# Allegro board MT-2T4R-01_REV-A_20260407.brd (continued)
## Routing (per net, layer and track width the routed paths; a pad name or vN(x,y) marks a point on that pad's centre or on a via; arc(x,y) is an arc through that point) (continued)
VDD12_MEM: length 12.6
  BOTTOM w0.2: 19.06,29.05 19.06,29.05 R64.2 C151.2
  BOTTOM w0.25: v2(20.7,9.01) U21.A9 21.13,9.44 v2(21.13,9.44) 21.13,9.87 U21.A11 v2(20.7,9.87) ; v2(20.7,9.01) U21.C9 U21.C11 v2(20.7,9.87) ; v2(20.7,9.01) 20.7,9.01 U21.B10 20.7,9.87 v2(20.7,9.87) ; U21.E13 v2(19.41,10.3) ; U21.D16 U21.E15
  BOTTOM w0.254: R87.2 C225.1 22.3,7.6 22.4,7.5 C223.1 22.05,7.05 21.7,7.4 21.7,8.44 U21.A9 ; U21.B10 v2(21.13,9.44) ; U21.E15 v2(19.41,11.18) ; U21.E11 v2(19.41,10.3)
  vias: v1(21.93,23.78) v1(21.99,24.12) v1(21.96,23.47) v1(22.24,23.79) v1(22.31,24.18) v1(22.28,23.4) v1(22.51,23.94) v1(22.5,23.61) v1(22.73,23.4) v1(22.79,23.7)
VIN_12V: length 12.8
  TOP w0.2: R102.1 v2(3.99,9.1)
  TOP w0.25: 6.38,18.52 6.57,18.33
  03-POWER w0.15: v2(6.66,18.17) 6.22,18.17 5.86,17.8 5.86,16.39 3.99,14.52 v2(3.99,9.1)
BOOT_SEL0: length 0.6
  TOP w0.3: 15.14,7.54 15.14,7.69 v2(15.11,7.72)
  BOTTOM w0.254: U21.P6 v2(15.11,7.72)
BOOT_SEL1: length 8.9
  TOP w0.3: 15.14,6.64 15.14,6.83 v2(15.11,6.86)
  BOTTOM w0.1: U21.N5 15.54,7.29 v2(15.11,6.86) 14.78,6.53 14.59,6.53 14.41,6.71 14.12,6.71 13.56,6.15 13.21,6.15 13.06,6.3 12.82,6.3 12.25,5.73 TP36.1 11.6,3.85 10.35,3.85 10.25,3.75 J3.3
BOOT_SEL2: length 1.3
  TOP w0.4: R100.2 15.14,5.97 v2(15.11,6)
  BOTTOM w0.1: v2(15.11,6) 15.54,6.42 U21.P4
BUCK_1V8: length 46.7
  TOP w0.25: v2(14.25,13.74) 14.15,13.64 C247.1
  TOP w0.3: v2(17.26,8.15) 17.45,7.96 C229.1 ; FB17.2 18.12,4.91 v2(18.12,5.1) 18.25,5.22 R94.2 R93.2 ; v2(15.97,12.88) 15.25,12.88 C232.1 ; v2(12.95,8.15) 13.37,7.73 C234.1
  TOP w0.35: FB16.1 C194.1 22.1,10.2 v2(21.88,9.98)
  03-POWER w0.1: v1(4.17,39.56) 4.17,39.56 9.64,39.56 v1(10.94,38.27) 12.22,39.55 12.22,39.56 20.66,39.56 v1(20.67,39.57)
  BOTTOM w0.1: U16.1 v1(20.67,39.57) ; U8.1 v1(4.17,39.56) ; v1(10.94,38.27) 10.94,36.01 10.58,35.66 C146.2
  BOTTOM w0.15: v2(11.67,6.04) 11.29,5.66 11.29,4.59 TP43.1 10.8,4.1 10.25,4.1 9.75,3.6 J3.4
  BOTTOM w0.2: C146.2 10.53,36.2 10.53,38.42 10.86,38.76 11.46,38.76 11.72,39.02 11.72,39.37 C140.2 R75.2
  BOTTOM w0.25: v2(14.25,13.74) U21.T20 U21.P20 ; v2(17.26,8.15) 17.26,8.15 U21.L7 ; U21.R17 U21.N17 v2(15.97,12.88)
  BOTTOM w0.254: U21.K8 v2(17.26,8.15) ; U21.AC3 v2(11.67,6.04) ; U21.T8 v2(14.68,8.15) ; U21.H2 v2(18.12,5.1) ; U21.AA7 v2(12.95,8.15) ; U21.C13 20.45,10.73 20.7,10.48 U21.B12 21.54,10.3 21.85,9.98 v2(21.88,9.98)
  BOTTOM w0.3: C146.2 9.98,35.28 v1(9.98,35.28) 9.98,35.15 v1(10.14,35)
  vias: v1(9.43,34.99) v1(9.47,34.38) v1(9.62,34.68) v1(9.66,35.27) v1(9.79,34.97) v1(9.8,34.39) v1(9.95,34.7) v1(10.13,34.45) v1(10.29,35.28) v1(10.28,34.72) v3(12.1,9.44)
BUCK_3V3: length 117.6
  TOP w0.3: R103.1 13.03,12.41 13.38,12.06 15.33,12.06 15.54,12.28 C193.1 15.97,12.08 v2(15.97,12.02) ; v2(13.39,8.58) 13.39,8.59 R101.2 13.33,8.99 13.78,8.99 14,8.77 C237.1 14.08,8.75 v2(14.25,8.58)
  TOP w0.35: R101.2 12.42,8.82 11.65,8.05 U19.8 11.35,8.22 11.35,9.71 12.26,10.62 12.26,12.25 R103.1
  TOP w0.4: v2(8.17,17.54) v2(8.61,17.54) ; v2(21.69,16.78) 21.26,16.78 v2(21.25,16.79)
  TOP w0.5: FB13.1 7.11,6.58 ; 7.11,6.58 7.21,6.68 9.54,6.68 C57.1 9.72,6.84 10.61,6.84 C254.1 11.18,7.41 U19.8 ; 7.11,6.58 6.49,7.2 6.49,8.86 7.64,10 v2(7.64,12.31) v2(7.64,12.79)
  03-POWER w0.4: v2(21.69,16.78) 21.26,16.78 v2(21.25,16.79) 21.25,25.39 21.05,25.59 21.05,28.87 21.68,29.5 v1(21.68,31.06) 22.82,32.19 22.82,40.19 21.63,41.38 4.23,41.38 2.84,39.98 2.84,36.14 3.69,35.29 4.39,35.29 v1(4.39,35.27) 4.71,34.95 v1(4.72,34.95)
  03-POWER w0.5: 8.27,17.2 8.27,17.44 v2(8.17,17.54) v2(8.61,17.54) 8.27,17.2 ; 8.27,17.2 8.27,15.76 7.64,15.13 v2(7.64,12.79) v2(7.64,12.31)
  BOTTOM w0.12: U11.1 21.6,30.98 v1(21.68,31.06)
  BOTTOM w0.2: C139.2 5.22,35.66 5.36,35.8 5.36,38.02 6.22,38.88 C141.2 R53.2
  BOTTOM w0.25: v2(7.64,12.79) 7.64,12.8 7.39,13.05 R97.2 ; U21.P16 v2(15.97,12.02)
  BOTTOM w0.254: U21.M16 v2(15.97,12.02) ; U21.U7 v2(14.25,8.58) ; U21.Y8 v2(13.39,8.58)
  BOTTOM w0.3: C139.2 v1(4.72,35.27)
  BOTTOM w0.4: v2(21.25,16.79) 21.26,16.78 v2(21.69,16.78) 22.9,16.78 23.32,16.36 FB12.1 ; v2(7.64,12.79) v2(7.64,12.31)
  BOTTOM w0.5: 8.52,17.89 8.52,20.29 6.4,22.42 6.4,25.6 5.29,26.71 5.29,34.38 v1(4.72,34.95) ; 8.52,17.89 8.52,17.62 v2(8.61,17.54) v2(8.17,17.54) 8.52,17.89
  vias: v1(4.4,34.96) v1(4.61,34.67) v1(4.92,34.67) v1(5.06,35.26) v1(5.07,34.95)
BUCK_CORE: length 18.7
  TOP w0.3: v2(12.53,7.72) 12.47,7.66 C244.1 ; FB18.2 17.95,5.74 v2(17.69,6) ; v2(16.4,13.31) 16.4,13.34 C249.2
  BOTTOM w0.1: C149.2 21.02,35.19 20.56,35.65 20.56,35.77
  BOTTOM w0.2: R61.2 C153.2 22.77,38.86 21.7,37.79 21.7,35.84 21.58,35.72 ; 21.52,35.66 C149.2
  BOTTOM w0.25: v2(17.69,11.16) 17.69,11.16 U21.H14 ; U21.G9 18.12,9.01 v2(18.12,9.01) ; U21.M10 16.83,9.44 v2(16.83,9.44) ; U21.P10 15.97,9.44 v2(15.97,9.44) ; v2(18.12,11.59) 18.12,11.59 U21.G15 ; U21.N13 15.54,10.73 v2(15.54,10.73) ; U21.R19 U21.N19 ; U21.G11 v2(18.12,9.87) ; v2(17.26,10.73) 17.26,10.73 U21.J13 ; U21.M14 15.97,11.16 v2(15.97,11.16)
  BOTTOM w0.254: U21.AB6 v2(12.53,7.72) ; U21.H16 v2(18.12,11.59) ; U21.H10 v2(18.12,9.01) ; U21.N19 v2(16.4,13.31) ; U21.N15 v2(15.97,11.16) ; U21.J15 v2(17.69,11.16) ; U21.J1 v2(17.69,6) ; U21.N9 v2(15.97,9.44) ; U21.J11 v2(18.12,9.87) ; v2(15.11,10.33) U21.R13 U21.R15 ; U21.P14 v2(15.54,10.73) ; U21.L9 v2(16.83,9.44) ; U21.K14 v2(17.26,10.73)
  vias: v1(20.67,35.72) v1(20.67,35.39) v1(20.68,35.07) v1(20.69,34.76) v1(20.69,34.44) v1(20.66,34.13) v1(20.99,35.73) v1(21,35.4) v1(21,35.08) v1(21.01,34.77) v1(21.01,34.45) v1(20.99,34.15) v1(21.31,35.73) v1(21.31,35.4) v1(21.32,35.08) v1(21.32,34.76) v1(21.33,34.45) v1(21.3,34.14) v1(21.63,35.73) v1(21.64,35.4) v1(21.64,35.08) v1(21.65,34.76) v1(21.63,34.14) v1(21.65,34.45) v1(21.95,35.73) v1(21.95,34.14) v1(21.95,35.4) v1(21.96,35.08) v1(21.97,34.77) v1(21.97,34.45)
CANH: length 15.5
  TOP w0.127: U12.7 5.1,2.61 4.98,2.73 3.19,2.73 2.15,3.77 2.15,4.25 R71.2 2.15,4.78 2.15,5.15 C133.2 2.14,5.67 2.14,6.18 2.9,6.93 3.28,6.93 6.55,10.21 6.55,10.45 6.44,10.57 v2(6.36,10.57)
  BOTTOM w0.102: J2.10 4.88,10.2 5.38,10.7 5.72,10.7 ESD15.1 5.98,10.7 6.23,10.7 v2(6.36,10.57)
CANL: length 15.6
  TOP w0.127: v2(6.36,11.19) 6.78,10.76 6.78,10.11 3.38,6.71 3,6.71 2.37,6.08 2.37,5.68 C134.1 2.38,5.16 2.38,4.77 R72.1 2.38,4.25 2.38,3.87 3.28,2.96 4.58,2.96 U12.6
  BOTTOM w0.1: v2(6.36,11.19) 6.25,11.07
  BOTTOM w0.102: 6.25,11.07 6.13,10.95 5.97,10.95 ESD16.1 5.72,10.94 5.38,10.94 4.88,11.45 J2.9
CASCADE: length 3.6
  02-GND1 w0.1: v4(13.21,20.81) 12.85,20.81 12.79,20.75 12.75,20.75 10.87,18.87 v2(10.87,18.82)
  BOTTOM w0.1: R57.2 10.81,18.77 v2(10.87,18.82)
CH_1V4: length 13.3
  BOTTOM w0.2: R51.1 C86.2 17.25,39 16.34,38.09 16.34,35.86 16.14,35.66 C88.1
  BOTTOM w0.3: 15.83,30.47 16.21,30.47 17.87,28.8 FB9.1 ; v1(7.79,30.34) 7.67,30.34 7.23,29.9 7.23,27.39 FB8.1
  vias: v1(7.81,31.08) v1(7.78,30.73) v1(8.04,30.52) v1(8.12,30.88) v1(14.09,31.3) v1(14.32,31.55) v1(14.53,31.33) v1(14.57,31.77) v1(14.77,31.53)
CH_1V8: length 0.3
  BOTTOM w0.1: FB3.1 8.72,29.37 v1(8.72,29.48)
  vias: v1(8.73,29.82) v1(8.78,30.11) v1(8.81,29.2) v1(9.03,29.94) v1(8.98,29.63) v1(9.11,29.27) v1(14.54,17.4) v1(14.79,17.59) v1(15.03,17.4) v1(15.28,17.59) v1(15.53,17.41) v1(15.82,17.59)
CKN_PHY: length 6.3
  TOP w0.076: 14.76,19.57 14.48,19.85 U1.N18
  TOP w0.1: 14.76,19.57 15.09,19.24
  TOP w0.127: 15.09,19.24 15.09,17.3 13.96,16.17 13.96,15.17 v2(13.82,15.03)
  BOTTOM w0.102: U21.V22 v2(13.82,15.03)
CKP_PHY: length 6.4
  TOP w0.1: U1.N19 14.8,19.85 14.92,19.74 15.32,19.34
  TOP w0.127: 15.32,19.34 15.32,17.21 14.19,16.08 14.19,14.66 v2(14.25,14.6)
  BOTTOM w0.102: U21.U21 v2(14.25,14.6)
D0N_PHY: length 7.3
  TOP w0.1: U1.L19 16.06,19.86
  TOP w0.127: v2(15.44,14.16) 15.44,14.79 15.24,15 15.24,15.4 16.06,16.22 16.06,19.86
  BOTTOM w0.102: U21.R21 15.44,14.17 v2(15.44,14.16)
D0P_PHY: length 7.3
  TOP w0.076: 15.68,20.53 15.68,20.56 15.44,20.81 U1.L18
  TOP w0.1: 15.68,20.53 16.13,20.08 16.15,20.08 16.28,19.95 16.28,19.89 16.29,19.87 16.29,19.86
  TOP w0.127: v2(15.6,15.25) 15.6,15.43 15.76,15.59 16.07,15.59 16.2,15.72 16.2,16.03 16.29,16.13 16.29,19.86
  BOTTOM w0.102: U21.R23 15.38,15.03 v2(15.6,15.25)
D1N_PHY: length 7.1
  TOP w0.1: U1.M19 15.16,20.17 15.26,20.07 15.26,19.98 15.15,19.87 15.15,19.82 15.24,19.74 15.36,19.74 15.43,19.81 15.52,19.81 15.59,19.74 15.59,19.59
  TOP w0.127: v2(14.61,15.03) 14.77,15.18 14.77,15.58 15,15.82 15,15.98 14.84,16.14 14.84,16.31 14.97,16.45 15.14,16.45 15.29,16.29 15.47,16.29 15.59,16.41 15.59,19.59
  BOTTOM w0.102: U21.U23 v2(14.61,15.03)
D1P_PHY: length 7.2
  TOP w0.076: U1.M18 15.12,20.49 15.41,20.2 15.45,20.17
  TOP w0.1: 15.82,19.79 15.45,20.17
  TOP w0.127: 15.82,19.79 15.82,16.32 15.17,15.66 14.99,15.49 14.99,14.61 v2(15.01,14.6)
  BOTTOM w0.102: v2(15.01,14.6) U21.T22
D2N_PHY: length 6.2
  TOP w0.076: U1.P18 14.16,19.53 14.45,19.25
  TOP w0.1: 14.61,19.09 14.45,19.25
  TOP w0.127: v2(12.96,15.03) 13.03,15.03 13.16,15.16 13.16,16.09 14.61,17.54 14.61,19.09
  BOTTOM w0.102: U21.W23 v2(12.96,15.03)
D2P_PHY: length 6.1
  TOP w0.1: U1.P19 14.73,19.29 14.73,19.29 14.84,19.18 14.84,19.03
  TOP w0.127: 14.84,19.03 14.84,17.45 13.39,16 v2(13.39,14.6)
  BOTTOM w0.102: U21.W21 v2(13.39,14.6)
D3N_PHY: length 5.9
  TOP w0.076: 14.1,18.96 13.85,19.22 U1.R18
  TOP w0.127: v2(12.1,15.03) 12.3,15.23 12.3,15.93 14.15,17.78 14.15,18.91 14.1,18.96
  BOTTOM w0.102: U21.AA23 v2(12.1,15.03)
D3P_PHY: length 5.9
  TOP w0.1: 14.25,19.14 14.17,19.22 U1.R19
  TOP w0.127: 14.25,19.14 14.38,19.01 14.38,17.69 12.53,15.84 v2(12.53,14.6)
  BOTTOM w0.102: U21.Y22 v2(12.53,14.6)
DDR_VREF: length 4.4
  BOTTOM w0.254: U21.A13 22.22,10.73 C224.1 R86.2 22.45,9.65 23.2,8.9 R87.1 23.1,8.7 22.4,8.7 C225.2
EXCLKI: length 3.7
  BOTTOM w0.1: Y4.1 15.18,3.55 15.5,3.55 C52.1 R18.1 16.61,4.66 16.61,4.93 U21.N1
EXCLKO: length 4.1
  BOTTOM w0.1: U21.N3 15.97,5.99 17,4.96 17,4.15 R18.2 R90.2
EXT_12V:
  vias: v2(1.79,27) v2(1.8,26.58) v2(1.8,26.16) v2(1.84,25.75) v2(2.22,26.99) v2(2.23,26.58) v2(2.23,26.15) v2(2.27,25.74) v2(2.65,26.98) v2(2.65,26.53) v2(2.68,26.1) v2(2.67,25.67) v2(3.09,27) v2(3.09,26.55) v2(3.12,26.1) v2(3.11,25.68)
INT: length 3.7
  TOP w0.076: 10.87,19.43 11.94,20.49 U1.T14
  TOP w0.1: TP28.1 10,18.33 10,18.98 10.28,19.26 10.71,19.26 10.87,19.43
MSC2_CLK: length 14.1
  BOTTOM w0.1: 11.32,10.26 11.47,10.41 11.76,10.41 11.93,10.58 12.25,10.58 12.41,10.42 12.64,10.42 12.95,10.73 U21.W13
  BOTTOM w0.155: 11.32,10.26 10.59,10.26 10.2,10.65 8.96,10.65 7.75,9.44 7.75,9 4.75,6 J3.14
MSC2_CMD: length 12.9
  BOTTOM w0.1: 11.2,9.59 11.78,9.59 11.95,9.76 12.24,9.76 12.43,9.57 12.65,9.57 12.82,9.74 13.13,9.74 13.26,9.87 U21.W11
  BOTTOM w0.155: J3.12 5.75,5.96 8.31,8.52 8.31,9.18 9.2,10.07 10.02,10.07 10.37,9.72 11.07,9.72 11.2,9.59
MSC2_D0: length 10.8
  BOTTOM w0.1: 11.37,9.29 11.82,9.29 11.98,9.13 12.21,9.13 12.38,9.29 12.81,9.29 U21.Y10
  BOTTOM w0.155: J3.9 7.25,3.75 6.92,4.08 6.92,5.79 9.15,8.02 9.15,8.77 9.33,8.95 11.03,8.95 11.37,9.29
MSC2_D1: length 13.3
  03-POWER w0.1: v2(10.63,9.33) 10.89,9.33 v1(11.66,8.56)
  BOTTOM w0.1: U21.V10 13.38,9.44 12.63,8.69 12.41,8.69 12.23,8.87 11.97,8.87 v1(11.66,8.56)
  BOTTOM w0.155: v2(10.63,9.33) 10.35,9.33 9.89,9.79 9.3,9.79 8.58,9.07 8.58,8.35 6.25,6.02 J3.11
MSC2_D2: length 11.3
  03-POWER w0.1: v3(12.96,10.3) 12.66,10 10.11,10 v2(9.48,9.37)
  BOTTOM w0.155: v2(9.48,9.37) 9.29,9.37 8.86,8.94 8.86,8.18 6.6,5.92 6.6,3.97 6.75,3.82 J3.10
MSC2_D3: length 14
  BOTTOM w0.1: U21.V12 13.39,10.3 13.1,10.01 12.84,10.01 12.68,10.17 12.38,10.17 12.2,9.99 11.96,9.99 11.78,10.17 11.56,10.17 11.38,9.99
  BOTTOM w0.155: J3.13 5.25,6 8.03,8.78 8.03,9.31 9.06,10.34 10.12,10.34 10.47,9.99 11.38,9.99
PB26/RST: length 6.8
  TOP w0.102: v2(17.7,13.74) 17.83,13.88 19.5,13.88 v2(21.12,15.49)
  BOTTOM w0.1: 17.7,13.7 17.94,13.46 18.4,13.46 U21.G19 ; R70.1 21.82,16.19 v2(21.12,15.49)
  BOTTOM w0.102: 17.7,13.7 17.7,13.73 v2(17.7,13.74)
PB27/INT: length 6.6
  TOP w0.102: v2(20.47,16.09) 18.78,17.77 U14.13
  BOTTOM w0.1: U21.C19 20.27,13.73 19.95,14.05 19.95,14.3 20.15,14.5 20.15,14.75 19.95,14.95 19.95,15.22 20.47,15.74 v2(20.47,16.09)
PB28/CS: length 1.8
  TOP w0.102: v2(18.55,14.6) 18.48,14.53 U14.18
  BOTTOM w0.1: 18.85,14.3 18.85,13.87 U21.F20
  BOTTOM w0.102: v2(18.55,14.6) 18.85,14.3
PB29/MISO: length 3
  BOTTOM w0.1: U21.F18 18.98,13.32 17.8,14.5 17.8,14.72 18.11,15.03 v2(18.11,15.24)
PB30/MOSI: length 4
  TOP w0.102: U14.16 18.91,15.82 v2(18.91,15.83)
  BOTTOM w0.1: U21.E19 19.3,13.42 19.3,13.85 19.1,14.05 19.1,14.25 19.3,14.45 19.3,14.7 18.99,15.01
  BOTTOM w0.102: 18.99,15.01 18.91,15.09 v2(18.91,15.83)
PB31/CLK: length 5.9
  TOP w0.102: v2(19.7,15.59) 19.7,16.34 18.91,17.12 U14.14
  BOTTOM w0.1: U21.D18 19.84,13.31 19.55,13.6 19.55,13.85 19.7,14 19.7,14.35 19.55,14.5 19.55,14.7 19.7,14.85 v2(19.7,15.59)
PC01/BEEP: length 12.4
  TOP w0.1: v2(11.16,14.82) 11.16,15.37 11.84,16.04 11.84,16.35 v2(12.06,16.57)
  BOTTOM w0.1: ESD20.1 6.09,16.34 11.84,16.34 v2(12.06,16.57) ; U21.Y20 12.51,13.74 11.43,14.82 v2(11.16,14.82)
  BOTTOM w0.155: J2.5 5.27,16.45 ESD20.1
PC02/LED_L: length 14.1
  TOP w0.1: v2(9.86,15.35) 10.96,16.45 v2(10.96,17.17)
  BOTTOM w0.1: ESD22.1 6.26,18.95 6.45,18.75 7.04,18.75 7.34,18.45 7.34,17.61 7.95,17 8.7,17 9.1,17.4 10.72,17.4 v2(10.96,17.17) ; v2(9.86,15.35) 9.74,15.23 9.74,14.38 U21.AC17
  BOTTOM w0.155: J2.3 ESD22.1
PC03/LED_R: length 13.5
  TOP w0.1: v2(8.75,14.8) 8.75,16.49 9.23,16.96 v2(9.23,17.02)
  BOTTOM w0.1: v2(8.75,14.8) 8.93,14.8 11.57,12.16 11.96,12.16 U21.AB16 ; v2(9.23,17.02) 8.96,16.75 7.91,16.75 7.11,17.55 7.11,18.32 6.9,18.53 6.45,18.53 5.63,17.7 ESD21.1
  BOTTOM w0.155: ESD21.1 4.59,17.56 J2.4
PC04/BACK_IN: length 11.6
  BOTTOM w0.1: U21.Y16 12.96,11.6 12.65,11.29 12.38,11.29 11.78,11.89 11.54,11.89 10.04,13.39 8.44,13.39 8.12,13.08 8.12,11.93 8.02,11.83 7.52,11.83 6.74,12.6 5.94,12.6 ESD17.1
  BOTTOM w0.155: J2.8 ESD17.1
PD05/CH_RST: length 31.7
  TOP w0.1: v2(12.78,17.29) 13.21,17.72 13.21,18.26
  BOTTOM w0.1: U21.B8 20.7,8.16 21.02,7.84 21.02,7.59 20.79,7.36 20.79,7.22 21.07,6.94 21.32,6.94 21.97,6.29 21.97,5.75 22.07,5.65 24.08,5.65 24.21,5.78 24.21,12.68 24.55,13.02 24.55,17.01 23.52,18.04 18.85,18.04 17.53,16.72 14.16,16.72 13.87,17.02 C51.2 13.21,17.29 R31.2 v2(12.78,17.29)
POR_BYPASS: length 4
  02-GND1 w0.1: v2(10.37,18.85) 10.37,18.85 10.69,19.17 10.79,19.17 12.74,21.12 v4(12.89,21.12)
  BOTTOM w0.1: v2(10.37,18.85) 10.37,18.85 10.15,18.63 R56.2
PPRST_N: length 4.4
  TOP w0.1: v2(19.84,7.28) 19.84,7.28 19.84,6.14 R93.1
  TOP w0.3: C252.2 v2(19.84,7.29)
  BOTTOM w0.1: U21.K6 17.68,7.72 17.98,7.42 18.25,7.42 18.41,7.58 18.69,7.58 19.26,7.01 19.61,7.01 19.73,7.13 19.73,7.13 19.84,7.24 v2(19.84,7.29)
RX1: length 5.9
  TOP w0.278: U1.K1 9.74,26.82 arc(9.62,27) 9.57,27.23 9.57,27.98 arc(9.67,28.47) 9.96,28.9 10.67,29.61 arc(10.94,30.02) 11.04,30.51 RX1.1
RX2: length 6.3
  TOP w0.278: U1.M1 8.75,26.54 arc(8.64,26.71) 8.6,26.9 8.6,29.63 arc(8.66,29.94) 8.84,30.2 arc(9.02,30.47) 9.08,30.79 RX2.1
RX3: length 7
  TOP w0.278: RX3.1 7.12,31.07 arc(7.19,30.72) 7.39,30.42 arc(7.56,30.16) 7.62,29.85 7.62,27.08 arc(7.75,26.45) 8.11,25.91 U1.P1
RX4: length 8.2
  TOP w0.278: RX4.1 5.16,31.18 arc(5.22,30.88) 5.39,30.62 6.33,29.68 arc(6.56,29.34) 6.64,28.93 6.64,26.92 arc(6.79,26.16) 7.22,25.52 U1.T1
RXCAN: length 26.9
  TOP w0.127: 23.75,13.88 23.2,13.88 22.99,13.66 22.67,13.66 22.41,13.4 22.41,12.64 23.18,11.87 23.18,6.78 21.76,5.36 21.76,4.9 22.03,4.64 22.03,4.18 18.88,1.02 12.81,1.02 12.34,1.5 12.34,2.6 12.08,2.86 11.92,2.86 11.77,3.02 11.77,3.89 U12.4
SFC0_CE_N: length 6.1
  TOP w0.1: v2(11.1,10.64) 11.59,11.13 11.59,12.75 11.99,13.15 12.26,13.15 R103.2 12.26,13.47 11.28,13.47 11.18,13.57 U19.1
  03-POWER w0.1: v3(12.1,10.3) 11.44,10.3 v2(11.1,10.64)
SFC0_CLK: length 5.4
  TOP w0.1: v2(10.01,11.08) 10.01,11.01 8.9,9.9 8.9,8.31 U19.6
  BOTTOM w0.1: v2(10.01,11.08) 11.16,11.08 11.51,10.73 U21.AC13
SFC0_DQ0: length 7.5
  TOP w0.1: U19.5 7.59,8.27 7.59,9.01 8.27,9.69 8.27,10.07 v2(9.28,11.08)
  BOTTOM w0.1: U21.AA13 12.41,10.85 11.96,10.85 11.77,11.04 11.5,11.04 11.1,11.44 9.65,11.44 v2(9.28,11.08)
SFC0_DQ1: length 5
  TOP w0.1: v2(10.11,14.67) 10.11,14.65 9.91,14.46 U19.2
  BOTTOM w0.1: v2(10.11,14.67) 10.11,14.45 12.53,12.03 U21.AA15
SFC0_DQ2: length 4.6
  TOP w0.1: v2(8.64,12.97) U19.3
  BOTTOM w0.1: v2(8.64,12.97) 8.83,13.16 9.99,13.16 11.56,11.59 U21.AC15
SFC0_DQ3_HOLD_N: length 5.7
  TOP w0.1: v2(10.67,11.79) 10.57,11.69 10.57,10.85 10.07,10.35 10.07,8.21 U19.7
  BOTTOM w0.1: U21.AB14 11.97,11.29 11.56,11.29 11.06,11.79 v2(10.67,11.79)
SPI_CLK: length 37.8
  TOP w0.1: v2(9.75,11.82) 9.75,12.49 10.47,13.22 10.47,15.41 11.32,16.26 11.32,17.89 11.82,18.39 12.07,18.39 U1.W17
  BOTTOM w0.1: v2(9.75,11.82) 9.52,11.82 4.24,6.54 4.24,2.62 4.86,2 13.66,2 14.21,1.45 17.13,1.45 18.69,3.01 18.69,5.43 U21.G1
SPI_CS: length 41.6
  TOP w0.076: 11.95,18.6 12.57,19.22 U1.U16
  TOP w0.1: v2(9.55,12.8) 9.37,12.99 9.37,16.24 11.72,18.59 11.95,18.59 11.95,18.6
  BOTTOM w0.1: U21.E3 19.41,6.01 19.72,5.71 19.72,5.33 19.12,4.73 19.12,2.84 17.33,1.05 14.01,1.05 13.5,1.56 4.7,1.56 3.83,2.43 3.83,6.74 9.55,12.46 v2(9.55,12.8)
SPI_MISO: length 39.1
  TOP w0.076: U1.V17 12.57,18.58 12.22,18.23
  TOP w0.1: v2(10.16,12.4) 10.72,12.95 10.72,15.31 11.58,16.17 11.58,17.75 12.02,18.19 12.18,18.19 12.22,18.23
  BOTTOM w0.1: v2(10.16,12.4) 9.82,12.4 4.03,6.61 4.03,2.53 4.78,1.78 13.57,1.78 14.11,1.25 17.22,1.25 18.91,2.94 18.91,5.07 U21.E1
SPI_MOSI: length 43
  TOP w0.1: U1.W16 11.73,18.9 9.12,16.29 9.12,12.63 v2(8.74,12.25)
  BOTTOM w0.1: U21.G3 18.97,6.43 19.27,6.73 19.57,6.73 20.13,6.17 20.13,5.86 19.96,5.69 19.96,5.22 19.33,4.59 19.33,2.74 17.44,0.85 13.88,0.85 13.4,1.32 4.62,1.32 3.62,2.33 3.62,6.87 8.74,12 v2(8.74,12.25)
TX1: length 7.6
  TOP w0.278: TX3.1 20.84,31.26 arc(20.67,30.41) 20.19,29.69 U1.A12
TX2: length 6.8
  TOP w0.278: U1.A10 15.99,26.77 16.19,26.97 arc(16.31,27.15) 16.36,27.37 arc(16.3,27.67) 16.13,27.92 13.25,30.8 arc(13.11,30.99) 13.02,31.21 arc(13.01,31.3) 13,31.39 TX2.1
TXCAN: length 26.9
  TOP w0.127: U14.1 23.2,13.22 22.98,13.44 22.77,13.44 22.64,13.31 22.64,12.74 23.41,11.97 23.41,6.68 21.99,5.26 21.99,5 22.26,4.73 22.26,4.08 18.97,0.79 12.72,0.79 12.11,1.41 12.11,2.5 11.98,2.63 11.91,2.63 11.76,2.49 11.76,1.46 11.24,0.94 U12.1
UART2_RXD: length 16.9
  TOP w0.1: v2(19.9,3.24) 19.54,3.24 17.97,1.67 13.51,1.67 13.3,1.88 13.3,2.7 12.79,3.21 12.79,3.63 v2(12.56,3.86)
  BOTTOM w0.1: U21.B4 20.85,6.71 20.85,6.28 21.01,6.13 21.01,5.91 20.81,5.71 20.81,3.53 TP37.1 19.95,3.24 v2(19.9,3.24)
  BOTTOM w0.102: J3.1 11.25,2.82 11.35,2.71 11.56,2.71 12.09,3.24 12.09,3.49 12.46,3.86 v2(12.56,3.86)
UART2_TXD: length 17
  TOP w0.1: v2(12.44,3.34) 12.44,3.22 13.09,2.56 13.09,1.77 13.39,1.47 18.14,1.47 19.51,2.84 20.03,2.84 20.32,3.13 v2(20.32,3.85)
  BOTTOM w0.1: TP38.1 20.57,4.29 20.57,5.74 20.41,5.9 20.41,6.1 20.57,6.26 20.57,6.58 20.27,6.88 U21.C5
  BOTTOM w0.102: v2(12.44,3.34) 12.44,3.3 11.63,2.5 11,2.5 10.75,2.75 J3.2
UART3_RXD: length 29
  BOTTOM w0.1: ESD18.1 6.75,13.95 R97.1 7,14.2 7,15.07 7.85,15.92 17.87,15.92 19.29,17.34 23.25,17.34 23.92,16.67 23.92,13.4 23.57,13.05 21.34,13.05 20.81,12.53 20.81,12.13 U21.B16
  BOTTOM w0.155: J2.7 ESD18.1
UART3_TXD: length 27.8
  BOTTOM w0.1: ESD19.1 6.77,15.2 7.71,16.13 17.78,16.13 19.2,17.55 23.36,17.55 24.12,16.79 24.12,13.3 23.62,12.8 21.48,12.8 U21.A17
  BOTTOM w0.155: J2.6 ESD19.1
USB_DN: length 7.6
  BOTTOM w0.102: 9.65,6.2 9.35,6.2 9.05,5.9 8.9,5.9 8.45,5.45 8.45,4.1 8.62,3.93 8.62,3.63 8.75,3.5 J3.6 ; 9.65,6.2 9.65,6.5 9.9,6.75 11.54,6.75 12.08,7.29 U21.AA5 ; 9.65,6.2 TP40.1
USB_DP: length 7.1
  BOTTOM w0.102: U21.AC5 11.67,7.22 11.44,6.99 9.8,6.99 9.48,6.67 9.48,6.67 9.41,6.6 9.1,6.6 ; 9.1,6.6 9.1,6.29 8.95,6.14 8.8,6.14 8.21,5.55 8.21,4 8.38,3.83 8.38,3.63 8.25,3.5 J3.7 ; 9.1,6.6 TP41.1
VSYS: length 12.1
  TOP w0.2: C257.1 1.41,15.7 0.68,14.97 0.68,13.14 C256.1 1.07,12.75 R11.1
  BOTTOM w0.1: 2.87,42.27 2.84,42.24 2.84,42.19 2.7,42.05 2.7,41.94 2.58,41.82 ; v1(12.41,42.09) 12.62,42.31 ; 12.62,42.31 C84.2 ; 12.62,42.31 12.49,42.31 v1(12.41,42.4) ; U8.4 2.27,41.44 2.49,41.66 2.49,41.71 2.8,42.02 v1(2.93,42.02) ; v1(2.47,41.93) 2.72,42.17 C142.1 ; C85.2 13.23,42.31 ; 13.23,42.31 v1(13.03,42.1) ; 13.23,42.31 13.14,42.31 v1(13.04,42.42)
  BOTTOM w0.15: R76.1 v1(10.82,42.31) ; R50.2 v1(16.5,42.31)
  BOTTOM w0.25: v2(9.82,4.36) 9.86,4.36 10.15,4.65 TP39.1 9.7,4.8 v2(9.55,4.65) 9.5,4.65 9.45,4.6 9.25,4.6 C136.2 9.25,4.2 J3.5
  vias: v1(2.19,42.65) v1(2.19,42.34) v1(2.18,42.03) v1(2.5,42.34) v1(2.59,42.66) v1(2.92,42.65) v1(2.92,42.32) v1(7.37,42.75) v1(7.38,42.44) v1(7.38,42.14) v1(7.7,42.78) v1(7.69,42.46) v1(7.69,42.15) v1(8.02,42.77) v1(8.01,42.46) v1(8,42.15) v1(12.4,42.7) v1(12.73,42.73) v1(12.72,42.42) v1(12.72,42.11) v1(13.05,42.72) v1(18.37,42.72) v1(18.38,42.4) v1(18.38,42.1) v1(18.7,42.74) v1(18.69,42.43) v1(18.69,42.12) v1(19.02,42.73) v1(19.01,42.43) v1(19,42.11) v1(23.44,33.27) v1(23.45,32.65) v1(23.45,32.96) v1(23.74,33.27) v1(23.76,32.96) v1(23.76,32.64) v1(24.05,33.28) v1(24.08,32.95) v1(24.07,32.63) v2(1.88,15.09) v2(1.89,14.68) v2(2.3,15.1) v2(2.31,14.68) v2(2.48,15.9) v2(2.47,15.49) v2(2.73,15.15) v2(2.89,15.94) v2(2.88,15.53) v2(9.53,4.08)
WKUP_N: length 3.6
  TOP w0.1: R94.1 18.55,6.47 v2(18.55,6.87) 19.06,6.87 C253.2
  BOTTOM w0.1: v2(18.55,6.87) 18.27,7.15 17.97,7.15 17.25,6.43 U21.L3
N2439824: length 3
  BOTTOM w0.2: C86.1 R51.2 16.3,41.15 R54.1 16.29,41.16 U10.5
N2464554: length 3.8
  TOP w0.1: U1.J19 16.07,21.02 16.4,20.69 17.35,20.69 17.85,21.19 18.07,21.19 C48.2 18.38,21.19 18.62,21.19 Y1.1
N2465035: length 4.9
  TOP w0.1: Y1.3 19.53,20.89 18.37,20.89 C49.2 18.09,20.88 17.96,20.88 17.48,20.39 16.28,20.39 15.86,20.81 U1.K19
N2479306: length 4.5
  TOP w0.076: 17.17,21.84 16.95,21.84 16.71,22.08 U1.G18
  TOP w0.1: R28.2 19,23.67 17.17,21.84
N2558545: length 5.6
  TOP w0.076: U1.H18 16.39,21.76 16.81,21.35 17,21.35
  TOP w0.1: 17,21.35 17.01,21.35 19.22,23.56 19.22,24.29 C50.2
N2669126: length 3.8
  BOTTOM w0.12: U10.1 15.17,40.06 14.69,40.54 14.69,41.84 R50.1
N2735799: length 7.3
  TOP w0.4: v2(21.57,13.55) 19.85,13.55 19.53,13.22 U14.20
  BOTTOM w0.4: v2(21.57,13.55) C128.2 C129.2 22.4,15.27 R70.2 FB12.2
N2735943: length 5.1
  TOP w0.1: U14.9 22.98,18.43 22.72,18.69 22.72,19.64 23.15,20.07 C131.2 22.87,20.43 22.87,21.59 Y2.1
N2735967: length 4.6
  TOP w0.1: U14.8 23.18,17.77 22.42,18.54 22.42,20.13 C130.2 22.57,20.32 22.57,20.75 Y2.3
N2736087: length 3.6
  TOP w0.25: C133.1 0.99,5.46 v2(1.51,5.98) ; v2(3.03,5.97) 3.54,5.47 C134.2
  BOTTOM w0.25: v2(3.03,5.97) 2.4,5.34 C135.1 2.14,5.34 v2(1.51,5.98)
N2736303: length 3.7
  TOP w0.25: v2(2.98,3.93) 3.54,4.48 R72.2 ; v2(1.41,3.93) 0.99,4.36 R71.1
  BOTTOM w0.25: v2(2.98,3.93) 2.93,3.93 C132.1 2.08,4.59 v2(1.41,3.93)
N2736527: length 1.3
  TOP w0.25: R73.1 3.84,0.94 U12.8
N2736623: length 2.1
  TOP w0.25: FB13.2 C137.2 5.1,5.66 U12.5
N2737540: length 2.9
  BOTTOM w0.2: C141.1 R53.1 R77.1 5.32,41.16 U8.5
N2737548: length 3.7
  BOTTOM w0.12: R76.2 9.19,42.01 9.19,40.57 9.67,40.1 U15.1
N2737552: length 2.9
  BOTTOM w0.2: U15.5 10.78,41.16 R74.2 10.8,41.14 R75.1 C140.1
N2739230: length 3
  BOTTOM w0.2: U16.5 21.82,41.16 R63.2 R61.1 C153.1
N2739406: length 3.3
  BOTTOM w0.2: U11.5 21.42,29.91 R67.2 20.68,29.87 C151.1 R64.1
N16675046: length 3.4
  BOTTOM w0.1: Y4.3 14.28,3.25 15.35,3.25 C53.1 R90.1
N16679120: length 2.5
  TOP w0.3: FB17.1 16.98,4.4 16.98,5.3 16.98,5.3 v2(17.25,5.57)
  BOTTOM w0.254: U21.L1 v2(17.25,5.57)
N16679422: length 1.4
  BOTTOM w0.155: U21.AC7 11.17,8.15 R40.1
N16679836: length 2.2
  TOP w0.3: v2(14.25,10.3) 14.07,10.48 C198.1 13.43,10.48 13.15,10.2 13.15,9.73 R101.1
  BOTTOM w0.254: U21.T12 v2(14.25,10.3)
N16679980: length 3.1
  TOP w0.3: v2(16.4,6.43) 16.15,6.18 C220.2 16.15,6.11 16.38,5.88 16.8,5.88 C265.1 17.52,6.6 FB18.1
  BOTTOM w0.254: U21.M2 v2(16.4,6.43)
N16679984: length 3.6
  TOP w0.25: FB16.2 21.2,11.85 v2(21.54,12.19)
  BOTTOM w0.254: v2(21.54,12.19) 21.87,12.52 22.23,12.52 C200.1 21.64,11.59 U21.A15
N16680310: length 1.8
  BOTTOM w0.15: U21.B14 22.11,11.16 R4.1
N16680330: length 1.8
  BOTTOM w0.155: U21.A5 21.31,7.29 22.4,6.2 R89.2
N16680520: length 0.8
  TOP w0.3: C210.1 14.05,9.65 v2(14.25,9.45)
  BOTTOM w0.254: v2(14.25,9.45) U21.U11
N16681692: length 1.4
  BOTTOM w0.155: C70.2 10.9,8.43 11.48,9.01 U21.AC9
N16704000: length 3.2
  TOP w0.2: U4.1 3.65,12.14 R12.1 2.5,11.82 R11.2 1.96,11.83 C256.2
N16708145: length 1.3
  TOP w0.3: U4.6 3.94,15.48 3.53,15.89 C263.2
N16719733: length 1.2
  TOP w0.2: R102.2 U4.2

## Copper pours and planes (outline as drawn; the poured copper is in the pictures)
DVDD14 on BOTTOM: 12.62,21.31 12.62,21.22 13.21,20.63 13.35,20.63 13.64,20.92 13.64,21.31 13.53,21.42 13.53,21.79 13.58,21.83 13.58,21.83 13.37,22.04 13.36,22.04
DVDD14 on 03-POWER: 15.28,27.16 14.83,27.16 14.27,26.6 14.27,26.41 14.45,26.23 14.45,26.12 13.43,25.11 13.43,24.55 13,24.11 12.76,24.11 12.63,24.24 12.55,24.24 10.04,21.73 10.51,21.25 10.74,21.02 13.59,21.02 14.05,21.49 14.05,22.22 15.12,23.29 16.09,23.29 16.33,23.53 16.33,24.04 16.05,24.31 16.05,25.65 15.89,25.81 15.89,26.56
DVDD18 on 03-POWER: 13.2,24.66 13.2,24.49 13,24.29 12.85,24.29 12.62,24.51 12.44,24.51 9.84,21.91 9.84,21.72 10.68,20.88 13.63,20.88 14.24,21.49 14.24,22.16 14.95,22.86 15.89,22.86 16.02,22.73 16.02,22.41 15.55,21.94 15.55,21.04 14.26,19.74 13.42,19.74 13.42,19.75 13.17,20.01 10.97,20.01 10.78,20.2 10.25,20.2 10.05,20.01 9.82,20.01 8.31,21.52 8.31,24.21 11.86,27.76 11.86,29.91 12.13,30.18 12.61,30.18 12.99,29.8 12.99,27.02 13.03,26.88 12.63,26.47 12.63,25.24
GND on TOP: 0.2,42.5 0.43,43.07 1,43.3 24,43.3 24.57,43.07 24.8,42.5 24.8,1 24.57,0.43 24,0.2 1,0.2 0.43,0.43 0.2,1 ; 1 cut-out
GND on BOTTOM: 0.2,42.5 0.43,43.07 1,43.3 24,43.3 24.57,43.07 24.8,42.5 24.8,1 24.57,0.43 24,0.2 1,0.2 0.43,0.43 0.2,1 ; 6 cut-outs
GND on 02-GND1, 03-POWER: 0.2,42.5 0.43,43.07 1,43.3 24,43.3 24.57,43.07 24.8,42.5 24.8,1 24.57,0.43 24,0.2 1,0.2 0.43,0.43 0.2,1
VDD12_MEM on TOP: 19.21,11.75 19.21,10.2 19.3,10.11 19.3,9.93 19.3,9.93 19.3,9.48 19.41,9.36 20,9.36 20.56,8.81 21.45,8.81 21.74,9.1 21.74,9.64 21.58,9.81 21.05,9.81 20.79,10.06 20.6,10.06 20.48,9.95 20.06,9.95 19.86,10.15 19.86,11.76 19.78,11.84 19.29,11.84
VDD12_MEM on BOTTOM: 16.47,34.39 16.47,30.94 19.94,27.47 19.94,25.24 21.95,23.24 22.84,23.24 22.96,23.36 22.96,23.75 21.02,25.69 21.02,27.64 18.32,30.34 18.32,31.69 18.22,31.79 17.67,31.79 17.32,32.14 17.32,34.29 17.22,34.39
VDD12_MEM on 03-POWER: 20.2,14.09 20.2,12.33 20.2,11.79 19.83,11.42 19.28,11.42 19.2,11.34 19.2,10.61 19.2,10.61 19.2,9.67 19.54,9.33 19.96,9.33 20.5,8.79 20.94,8.79 21.39,9.24 21.39,9.87 21.22,10.04 21.22,13.58 23.49,15.86 23.49,23.74 22.83,24.41 21.95,24.41 21.81,24.26 21.81,23.36 21.93,23.23 22.3,23.23 22.54,23 22.54,16.43
VIN_12V on TOP: 5.44,16.53 5.44,14.52 5.61,14.35 6.05,14.35 6.29,14.58 6.29,17.23 6.92,17.86 6.92,19.15 6.64,19.43 5.37,19.43 5.29,19.34 5.29,16.68
BUCK_1V8 on BOTTOM: 6.16,36.02 10.15,36.02 10.55,35.62 10.55,34.05 10.47,33.97 9.41,33.97 9.33,34.04 9.33,34.84 9.22,34.95 6.2,34.95 6.08,35.07 6.08,35.93
BUCK_1V8 on 03-POWER: 10.33,35.48 9.59,35.48 6.18,32.06 6.18,26.13 5.38,25.33 5.38,21.16 4.51,20.29 4.51,16.31 2.68,14.49 2.68,7.45 4.07,6.06 4.07,3.37 4.72,2.72 8.77,2.72 8.9,2.85 8.9,4.9 9.5,5.5 15.66,5.5 16.79,4.36 19,4.36 22.62,7.99 22.62,9.95 22.3,10.28 21.78,10.28 21.67,10.16 21.67,9.32 20.92,8.57 17.35,8.57 17.01,8.23 17.01,8.08 18.1,6.99 18.1,5.78 17.87,5.56 17.47,5.56 17.13,5.9 17.13,6.55 16.27,7.41 15.86,7.41 14.92,8.35 12.84,8.35 12.73,8.25 12.73,8.08 12.89,7.92 12.89,7.48 12.77,7.35 12.32,7.35 12.16,7.52 12.16,8.53 13.51,9.88 13.51,10.73 15.5,12.72 16.07,12.72 16.14,12.8 16.14,13.01 16.02,13.13 16.02,15.47 15.33,16.16 10.86,16.16 9.31,17.7 9.31,18.36 6.72,20.95 6.72,24.83 7.33,25.44 7.33,31.43 10.49,34.59 10.49,35.32
BUCK_3V3 on BOTTOM: 0.89,36.02 5.07,36.02 5.23,35.86 5.23,34.72 5,34.49 4.56,34.49 4.1,34.95 0.93,34.95 0.81,35.07 0.81,35.93
BUCK_3V3 on 03-POWER: 4.16,35.38 4.16,34.82 4.48,34.5 5.03,34.5 5.27,34.74 5.27,35.35 5.11,35.51 4.28,35.51
BUCK_CORE on TOP: 17.6,8.48 17.6,10.1 17.09,10.62 17.09,11.48 17.38,11.78 18.45,11.78 18.71,11.51 18.71,11.26 18.2,10.75 18.2,10.16 18.32,10.04 18.32,8.67 18.1,8.45 17.63,8.45
BUCK_CORE on TOP: 14.63,10.71 14.63,10.27 14.73,10.17 15.72,10.17 15.84,10.05 15.84,9.71 15.67,9.55 15.49,9.55 15.45,9.51 15.45,9.24 15.57,9.11 16.83,9.11 17.03,9.31 17.03,9.53 16.88,9.68 16.67,9.68 16.31,10.04 16.31,11.36 15.98,11.69 15.55,11.69 15.47,11.6 15.47,11.1 15.14,10.78 14.7,10.78
BUCK_CORE on BOTTOM: 17.19,36.02 21.88,36.02 22.12,35.77 22.12,34.08 22.02,33.97 20.56,33.97 20.49,34.03 20.49,34.73 20.28,34.95 17.23,34.95 17.11,35.07 17.11,35.93
BUCK_CORE on 03-POWER: 22.14,35.78 22.14,33.9 20.49,32.25 20.49,19.38 20.68,19.19 20.68,16.64 21.1,16.22 21.1,15.28 20,14.18 20,11.89 19.68,11.56 19.22,11.56 19,11.34 19,9.51 18.18,8.69 17.21,8.69 16.84,8.32 16.84,8.03 17.95,6.93 17.95,5.83 17.85,5.72 17.52,5.72 17.37,5.87 17.37,6.81 16.57,7.61 16.1,7.61 15.82,7.88 15.82,8.29 15.06,9.06 15.06,9.8 14.34,10.53 14.09,10.53 13.95,10.38 13.95,9.63 12.6,8.28 12.6,7.97 12.75,7.82 12.75,7.61 12.64,7.5 12.44,7.5 12.28,7.66 12.28,8.37 13.66,9.76 13.66,10.71 13.87,10.92 14.41,10.92 15.26,11.77 15.26,12.16 15.73,12.64 16.13,12.64 16.25,12.76 16.25,13.11 16.2,13.16 16.2,15.84 17.61,17.25 17.61,19.1 17.91,19.4 17.91,21.44 17.61,21.74 17.61,33.19 20.4,35.98 21.94,35.98
CH_1V4 on BOTTOM: 11.72,36.02 15.71,36.02 15.97,35.76 15.97,30.26 15.45,29.75 15.37,29.75 13.93,31.18 13.93,31.4 14.92,32.39 14.92,34.79 14.76,34.95 11.75,34.95 11.63,35.07 11.63,35.93
CH_1V4 on BOTTOM: 6.76,27.4 6.76,27.35 7.12,27 7.25,27 7.51,27.25 7.51,29.73 8.27,30.5 8.27,30.97 7.99,31.24 7.69,31.24 7,30.55 7,27.63
CH_1V4 on 03-POWER: 7.71,30.19 7.93,30.19 9.03,31.3 10.96,31.3 11.1,31.15 14.9,31.15 15.07,31.32 15.07,31.85 14.93,31.99 11.44,31.99 11.37,32.07 8.44,32.07 7.63,31.26 7.63,30.27
CH_1V8 on BOTTOM: 8.92,28.84 8.56,29.2 8.56,32.45 9.39,33.27 10.28,33.27 10.3,33.26 10.3,32.42 10.41,32.3 10.84,32.3 10.86,32.28 10.86,30.75 10.78,30.67 10.42,30.67 10.19,30.89 10.19,31.44 10.07,31.56 9.51,31.56 9.34,31.39 9.34,29.25
CH_1V8 on 03-POWER: 15.94,17.18 14.06,17.18 13,18.24 9.98,18.24 7.29,20.93 7.29,24.67 8.47,25.85 8.47,30.17 8.64,30.34 9.03,30.34 9.38,29.99 9.38,25.71 8.01,24.35 8.01,21.33 9.9,19.44 11.99,19.44 12.24,19.19 14.25,19.19 15.12,18.32 16.03,18.32 16.2,18.15 16.2,17.44
EXT_12V on TOP: 3.44,25.53 3.44,27.22 3.26,27.39 0.62,27.39 0.58,27.36 0.58,25.96 0.55,25.93 0.55,24.42 0.85,24.12 0.85,23.81 0.46,23.42 0.46,20.17 0.57,20.06 1.52,20.06 1.86,20.4 1.86,22.84 2.41,23.39 2.41,24.51
EXT_12V on BOTTOM: 1.84,25.4 1.59,25.64 1.59,27.14 1.67,27.22 3.89,27.22 5.77,25.33 5.77,21.52 5.3,21.04 3.6,21.04 3.56,21.08 3.56,22.04 4.35,22.83 4.35,24.83 3.78,25.4
VSYS on TOP: 0.88,15.32 1.73,14.47 3.05,14.47 3.14,14.56 3.14,15.99 2.82,16.31 2.43,16.31 2.11,16.64 2.11,19.55 1.94,19.72 0.88,19.72
VSYS on TOP: 9.3,4.7 9.3,3.75 9.9,3.15 11.35,3.15 11.5,3.3 11.5,3.65 11.35,3.8 10.3,3.8 10.05,4.05 10.05,4.45 9.65,4.85 9.45,4.85
VSYS on BOTTOM: 7.19,42.82 7.19,40.88 7.41,40.66 8.09,40.66 8.18,40.75 8.18,42.88 8.1,42.95 7.32,42.95
VSYS on BOTTOM: 12.88,41.81 12.88,40.63 12.91,40.6 13.59,40.6 13.86,40.88 13.86,42.63 13.6,42.89 12.82,42.89 12.82,42.89 12.31,42.89 12.22,42.8 12.22,41.97 12.28,41.91 12.79,41.91
VSYS on BOTTOM: 24.12,33.46 22.18,33.46 21.96,33.24 21.96,32.56 22.05,32.47 24.18,32.47 24.25,32.55 24.25,33.33
VSYS on BOTTOM: 18.19,42.79 18.19,40.85 18.41,40.63 19.09,40.63 19.18,40.72 19.18,42.84 19.1,42.91 18.32,42.91
VSYS on BOTTOM: 1.85,41.6 1.85,40.69 1.91,40.63 2.59,40.63 2.72,40.76 2.72,41.23 3.08,41.58 3.08,42.73 2.99,42.81 2.11,42.81 2.03,42.73 2.03,41.77
VSYS on BOTTOM: 1.74,14.37 2.51,14.37 3.19,15.05 3.19,16.11 3.07,16.24 2.39,16.24 1.6,15.45 1.6,14.51
VSYS on BOTTOM: 8.87,4.18 9.24,3.81 9.55,3.81 10.28,4.54 10.28,4.84 10.14,4.98 10.06,4.98 10,4.93 9.53,4.93 9.34,4.73 8.92,4.73 8.87,4.68
VSYS on 03-POWER: 2.52,14.51 2.52,7.38 3.91,5.99 3.91,3.35 5.14,2.12 8.62,2.12 9.29,2.78 9.29,4.73 9.43,4.88 9.8,4.88 10.17,4.5 10.17,2.22 9.18,1.23 4.7,1.23 2.3,3.63 2.3,4.45 1.04,5.71 1.04,15.17 0.79,15.43 0.79,40.71 2.02,41.94 2.02,42.75 2.35,43.08 22.48,43.08 24.31,41.25 24.31,32.61 24.1,32.4 23.29,32.4 23.14,32.54 23.14,40.52 21.98,41.69 4.11,41.69 2.54,40.12 2.54,34.6 6.03,31.12 6.03,26.34 5.19,25.5 5.19,21.2 4.35,20.37 4.35,16.34
N2440064 on BOTTOM: 13.62,39.42 13.62,38.24 13.85,38.02 13.85,37.36 13.7,37.21 11.78,37.21 11.65,37.34 11.65,37.88 11.79,38.02 12.6,38.02 13.02,38.45 13.02,39.37 13.09,39.43 13.61,39.43
N2737610 on BOTTOM: 8.07,39.42 8.07,38.24 8.29,38.02 8.29,37.36 8.14,37.21 6.23,37.21 6.1,37.34 6.1,37.88 6.24,38.02 7.04,38.02 7.47,38.45 7.47,39.37 7.53,39.43 8.05,39.43
N2737826 on BOTTOM: 2.57,39.43 2.57,38.47 3.02,38.02 3.02,37.36 2.87,37.21 0.96,37.21 0.83,37.34 0.83,37.88 0.97,38.02 1.55,38.02 1.97,38.44 1.97,39.41 1.99,39.44 2.57,39.44
N2738138 on TOP: 3.26,21.83 3.26,20.06 7.06,20.06 7.98,19.14 7.98,18.4 8.24,18.15 9.4,18.15 9.49,18.23 9.49,20.09 7.57,22 3.44,22
N2739292 on BOTTOM: 19.1,39.42 19.1,38.24 19.32,38.02 19.32,37.36 19.17,37.21 17.26,37.21 17.13,37.34 17.13,37.88 17.27,38.02 18.07,38.02 18.5,38.45 18.5,39.37 18.56,39.43 19.08,39.43
N2739468 on BOTTOM: 20.77,32.59 19.72,32.59 19.32,32.19 18.67,32.19 18.57,32.29 18.57,34.24 18.72,34.39 19.22,34.39 19.37,34.24 19.37,33.64 19.82,33.19 20.72,33.19 20.77,33.14
N16703806 on TOP: 4.59,14.35 4.59,15.27 3.88,15.98 3.88,19.57 4.05,19.74 4.74,19.74 5.11,19.37 5.11,16.55 5.18,16.48 5.18,14.4 5.12,14.34 4.59,14.34

Small or netless copper shapes (teardrops, artwork), in the pictures only: 1 on BOTTOM

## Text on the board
Ref Des/Silkscreen Bottom: GND | RXD | TXD | VBUS | 1V8 | BOOT | DN | DP | MT-2T4R-01 | 20260407 | REV-A
User.Comments: CR_UNNAMED1_4 | CR_UNNAMED_40 | CR_UNNAMED_35 | CR_UNNAMED_30 | CR_UNNAMED_41 | CR_UNNAMED_25 | CR_UNNAMED_36 | CR_UNNAMED_31 | CR_UNNAMED_42 | CR_UNNAMED_26 | CR_UNNAMED_37 | CR_UNNAMED_32 | CR_UNNAMED2_4 | CR_UNNAMED_43 | CR_UNNAMED_27 | CR_UNNAMED_33 | CR_UNNAMED2_3 | CR_UNNAMED_38 | CR_UNNAMED_44 | CR_UNNAMED_34 | CR_UNNAMED_28 | CR_UNNAMED_39 | CR_UNNAMED_29 | CR_UNNAMED_1 | CR_UNNAMED_2 | CR_UNNAMED_3 | CR_UNNAMED_15 | CR_UNNAMED_16 | CR_UNNAMED2_2 | CR_UNNAMED_17 | CR_UNNAMED_18 | CR_UNNAMED_19 | CR_UNNAMED_20 | CR_UNNAMED_21 | CR_UNNAMED_22 | CR_UNNAMED_23 | CR_UNNAMED_24
User.13: FIGURE | SIZE | 0.2 | 2.0 | DRILL CHART: TOP to BOTTOM | ALL UNITS ARE IN MILLIMETERS | PLATED | QTY | 460 | 4
User.16: FIGURE | SIZE | 0.15 | DRILL CHART: TOP to 02-GND1 | ALL UNITS ARE IN MILLIMETERS | PLATED | QTY | 659
User.18: FIGURE | SIZE | 0.15 | DRILL CHART: 03-POWER to BOTTOM | ALL UNITS ARE IN MILLIMETERS | PLATED | QTY | 3 | 423
